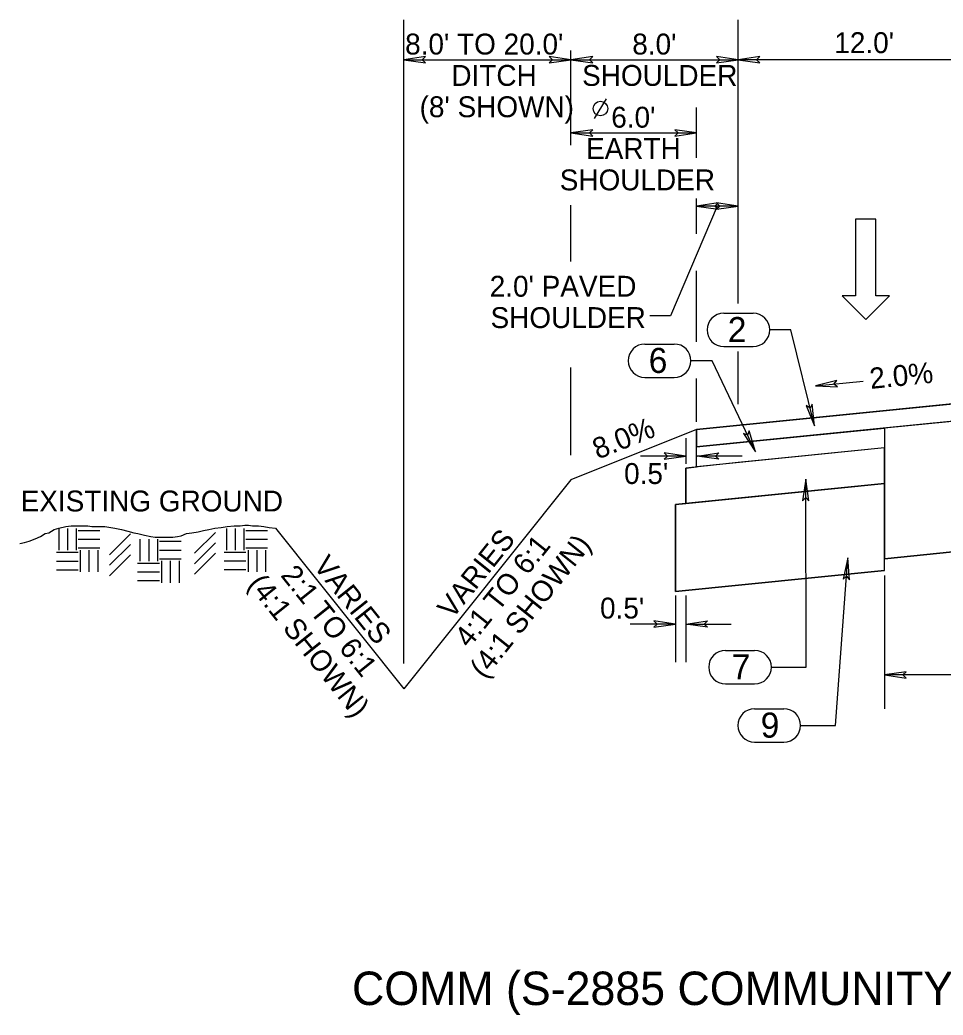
# Model space of a CAD drawing. Extents: x 2003207 to 2014043, y 843846 to 860154.
# Drawn here: x 2013826.45 to 2013870.63, y 844709.91 to 844757.53 of the extents above; entities that cross this region are included whole.
import ezdxf

# ---------------------------------------------------------------- set-up
doc = ezdxf.new("R2010")
doc.units = 0
for name, color, linetype in [('RD_EX_Road', 7, 'Continuous'), ('RD_EX_Road_txCode', 7, 'Continuous'), ('RD_QTY_Base_Course', 7, 'Continuous'), ('RD_QTY_ConcPave', 7, 'Continuous'), ('RD_QTY_Intermediate', 7, 'Continuous'), ('RD_QTY_PermVeg', 7, 'Continuous'), ('RD_QTY_Surf_Course', 7, 'Continuous'), ('RD_TX_Misc2', 7, 'Continuous'), ('RD_TX_TypSect', 7, 'Continuous'), ('RD_XS_ExGround', 7, 'Continuous')]:
    doc.layers.add(name, color=color, linetype=linetype)

msp = doc.modelspace()

# ---------------------------------------------------------------- linework, layer by layer
at = {"layer": 'RD_EX_Road'}
for p, q in [((2013881.821, 844739.393), (2013867.821, 844737.993)), ((2013867.821, 844737.993), (2013867.821, 844731.743)), ((2013881.821, 844733.143), (2013867.821, 844731.743)), ((2013867.821, 844731.743), (2013880.546, 844733.015))]:
    msp.add_line(p, q, dxfattribs=at)
at = {"layer": 'RD_QTY_Base_Course'}
for p, q in [((2013867.821, 844737.045), (2013860.821, 844736.345)), ((2013867.821, 844736.246), (2013867.821, 844737.045)), ((2013860.821, 844736.345), (2013858.321, 844736.083)), ((2013858.321, 844736.083), (2013858.321, 844734.391)), ((2013867.821, 844735.413), (2013867.821, 844736.246)), ((2013867.821, 844735.341), (2013867.821, 844735.413)), ((2013858.321, 844734.391), (2013867.821, 844735.341)), ((2013867.821, 844735.341), (2013860.821, 844734.641)), ((2013867.821, 844735.341), (2013867.821, 844735.341)), ((2013860.821, 844734.641), (2013857.821, 844734.341)), ((2013857.821, 844734.341), (2013858.321, 844734.391)), ((2013857.821, 844734.341), (2013857.821, 844730.174)), ((2013857.821, 844730.174), (2013857.821, 844734.341)), ((2013867.821, 844731.174), (2013857.821, 844730.174))]:
    msp.add_line(p, q, dxfattribs=at)
msp.add_lwpolyline([(2013857.821, 844730.174), (2013867.821, 844731.174), (2013867.821, 844735.341)], dxfattribs=at)
at = {"layer": 'RD_QTY_ConcPave'}
for p, q in [((2013858.321, 844736.083), (2013858.821, 844736.145)), ((2013858.321, 844734.391), (2013858.321, 844736.083)), ((2013867.821, 844735.341), (2013858.321, 844734.391))]:
    msp.add_line(p, q, dxfattribs=at)
at = {"layer": 'RD_QTY_Intermediate'}
for p, q in [((2013858.821, 844736.145), (2013858.821, 844737.092)), ((2013867.821, 844737.045), (2013858.821, 844736.145))]:
    msp.add_line(p, q, dxfattribs=at)
msp.add_lwpolyline([(2013858.821, 844737.092), (2013867.821, 844737.993), (2013867.821, 844737.045), (2013858.821, 844736.145)], close=True, dxfattribs=at)
at = {"layer": 'RD_QTY_PermVeg'}
for p, q in [((2013858.821, 844737.926), (2013852.821, 844735.526)), ((2013852.821, 844735.526), (2013844.821, 844725.526)), ((2013838.674, 844733.21), (2013844.821, 844725.526))]:
    msp.add_line(p, q, dxfattribs=at)
at = {"layer": 'RD_QTY_Surf_Course'}
for p, q in [((2013892.321, 844741.276), (2013858.821, 844737.926)), ((2013867.821, 844737.992), (2013858.821, 844737.092)), ((2013858.821, 844737.926), (2013858.821, 844737.092))]:
    msp.add_line(p, q, dxfattribs=at)
msp.add_lwpolyline([(2013858.821, 844737.926), (2013892.321, 844741.276), (2013925.821, 844737.926), (2013925.821, 844737.092), (2013892.321, 844740.442), (2013885.99, 844739.809), (2013885.99, 844738.976), (2013881.821, 844739.393), (2013858.821, 844737.092)], close=True, dxfattribs=at)
at = {"layer": 'RD_TX_Misc2'}
for p, q in [((2013860.134, 844743.494), (2013861.534, 844743.494)), ((2013856.361, 844742.02), (2013857.761, 844742.02)), ((2013860.134, 844741.894), (2013861.534, 844741.894)), ((2013856.361, 844740.42), (2013857.761, 844740.42)), ((2013860.21, 844727.356), (2013861.61, 844727.356)), ((2013860.21, 844725.756), (2013861.61, 844725.756)), ((2013861.609, 844724.568), (2013863.009, 844724.568)), ((2013861.609, 844722.968), (2013863.009, 844722.968))]:
    msp.add_line(p, q, dxfattribs=at)
for centre, start, end in [((2013860.134, 844742.694), 90, 270), ((2013861.534, 844742.694), 270, 90), ((2013856.361, 844741.22), 90, 270), ((2013857.761, 844741.22), 270, 90), ((2013860.21, 844726.556), 90, 270), ((2013861.61, 844726.556), 270, 90), ((2013861.609, 844723.768), 90, 270), ((2013863.009, 844723.768), 270, 90)]:
    msp.add_arc(centre, 0.8, start, end, dxfattribs=at)
at = {"layer": 'RD_TX_TypSect'}
for p, q in [((2013844.821, 844726.732), (2013844.821, 844757.53)), ((2013860.821, 844743.964), (2013860.821, 844757.53)), ((2013860.821, 844747.835), (2013860.821, 844757.53)), ((2013852.821, 844751.533), (2013852.821, 844756.062)), ((2013844.821, 844755.623), (2013852.821, 844755.623)), ((2013852.821, 844755.623), (2013860.821, 844755.623)), ((2013872.821, 844755.623), (2013860.821, 844755.623)), ((2013853.949, 844752.816), (2013854.515, 844753.759)), ((2013858.821, 844750.922), (2013858.821, 844753.33)), ((2013852.821, 844752.123), (2013858.821, 844752.123)), ((2013858.821, 844747.285), (2013858.821, 844748.978)), ((2013852.821, 844745.975), (2013852.821, 844748.661)), ((2013860.821, 844748.623), (2013858.821, 844748.623)), ((2013858.821, 844742.131), (2013858.821, 844745.518)), ((2013860.821, 844739.519), (2013860.821, 844741.656)), ((2013860.821, 844739.146), (2013860.821, 844741.562)), ((2013852.821, 844736.699), (2013852.821, 844740.897)), ((2013858.821, 844738.664), (2013858.821, 844740.367)), ((2013858.821, 844738.302), (2013858.821, 844740.229)), ((2013864.526, 844740.015), (2013866.803, 844740.243)), ((2013858.321, 844737.52), (2013858.321, 844736.291)), ((2013858.321, 844736.66), (2013856.154, 844736.66)), ((2013861.019, 844736.66), (2013858.851, 844736.66)), ((2013867.821, 844730.946), (2013867.821, 844724.555)), ((2013857.821, 844729.991), (2013857.821, 844726.789)), ((2013858.321, 844729.991), (2013858.321, 844726.789)), ((2013857.821, 844728.619), (2013855.654, 844728.619)), ((2013858.321, 844728.619), (2013860.489, 844728.619)), ((2013895.821, 844726.187), (2013867.821, 844726.187))]:
    msp.add_line(p, q, dxfattribs=at)
for points in [[(2013844.821, 844755.623), (2013845.86, 844755.473), (2013845.7, 844755.623), (2013845.86, 844755.773)], [(2013852.821, 844755.623), (2013851.783, 844755.773), (2013851.943, 844755.623), (2013851.783, 844755.473)], [(2013852.821, 844755.623), (2013853.86, 844755.473), (2013853.7, 844755.623), (2013853.86, 844755.773)], [(2013860.821, 844755.623), (2013859.783, 844755.773), (2013859.943, 844755.623), (2013859.783, 844755.473)], [(2013860.821, 844755.623), (2013861.86, 844755.473), (2013861.7, 844755.623), (2013861.86, 844755.773)], [(2013852.821, 844752.123), (2013853.86, 844751.973), (2013853.7, 844752.123), (2013853.86, 844752.273)], [(2013858.821, 844752.123), (2013857.783, 844752.273), (2013857.943, 844752.123), (2013857.783, 844751.973)], [(2013858.821, 844748.623), (2013859.86, 844748.473), (2013859.7, 844748.623), (2013859.86, 844748.773)], [(2013860.821, 844748.623), (2013859.783, 844748.773), (2013859.943, 844748.623), (2013859.783, 844748.473)], [(2013867.403, 844747.998), (2013866.443, 844747.998), (2013866.443, 844744.33), (2013865.792, 844744.33), (2013866.923, 844743.198), (2013868.055, 844744.33), (2013867.403, 844744.33)], [(2013864.526, 844740.015), (2013865.574, 844739.969), (2013865.4, 844740.102), (2013865.544, 844740.267)], [(2013864.468, 844738.101), (2013864.366, 844739.146), (2013864.259, 844738.955), (2013864.075, 844739.074)], [(2013861.654, 844736.865), (2013861.341, 844737.866), (2013861.275, 844737.657), (2013861.071, 844737.737)], [(2013858.321, 844736.66), (2013857.283, 844736.81), (2013857.443, 844736.66), (2013857.283, 844736.51)], [(2013858.851, 844736.66), (2013859.89, 844736.81), (2013859.73, 844736.66), (2013859.89, 844736.51)], [(2013864.052, 844735.553), (2013863.905, 844734.514), (2013864.054, 844734.674), (2013864.205, 844734.515)], [(2013866.069, 844731.789), (2013865.843, 844730.764), (2013866.004, 844730.912), (2013866.142, 844730.742)], [(2013857.821, 844728.619), (2013856.783, 844728.769), (2013856.943, 844728.619), (2013856.783, 844728.47)], [(2013858.321, 844728.619), (2013859.36, 844728.769), (2013859.2, 844728.619), (2013859.36, 844728.47)], [(2013867.821, 844726.187), (2013868.86, 844726.037), (2013868.7, 844726.187), (2013868.86, 844726.336)]]:
    msp.add_lwpolyline(points, close=True, dxfattribs=at)
for points in [[(2013859.821, 844748.623), (2013857.581, 844743.376), (2013856.594, 844743.376)], [(2013864.468, 844738.101), (2013863.343, 844742.694), (2013862.334, 844742.694)], [(2013861.654, 844736.865), (2013859.57, 844741.22), (2013858.561, 844741.22)], [(2013862.41, 844726.556), (2013864.075, 844726.556), (2013864.052, 844735.553)], [(2013863.809, 844723.768), (2013865.474, 844723.768), (2013866.069, 844731.789)]]:
    msp.add_lwpolyline(points, dxfattribs=at)
msp.add_circle((2013854.232, 844753.288), 0.35, dxfattribs=at)
at = {"layer": 'RD_XS_ExGround'}
for p, q in [((2013828.304, 844733.189), (2013828.304, 844732.148)), ((2013828.721, 844733.189), (2013828.721, 844732.148)), ((2013829.138, 844733.189), (2013829.138, 844732.148)), ((2013829.234, 844733.092), (2013830.276, 844733.092)), ((2013834.809, 844732.003), (2013835.809, 844733.003)), ((2013836.331, 844733.194), (2013836.331, 844732.152)), ((2013836.748, 844733.194), (2013836.748, 844732.152)), ((2013837.164, 844733.194), (2013837.164, 844732.152)), ((2013837.261, 844733.097), (2013838.303, 844733.097)), ((2013829.234, 844732.676), (2013830.276, 844732.676)), ((2013830.74, 844731.93), (2013831.74, 844732.93)), ((2013832.195, 844732.675), (2013832.195, 844731.634)), ((2013832.612, 844732.675), (2013832.612, 844731.634)), ((2013833.028, 844732.675), (2013833.028, 844731.634)), ((2013833.125, 844732.579), (2013834.166, 844732.579)), ((2013837.261, 844732.68), (2013838.303, 844732.68)), ((2013828.192, 844732.051), (2013829.234, 844732.051)), ((2013829.234, 844732.259), (2013830.276, 844732.259)), ((2013829.338, 844732.155), (2013829.338, 844731.113)), ((2013829.755, 844732.155), (2013829.755, 844731.113)), ((2013830.172, 844732.155), (2013830.172, 844731.113)), ((2013830.74, 844731.43), (2013831.74, 844732.43)), ((2013833.125, 844732.162), (2013834.166, 844732.162)), ((2013834.809, 844731.503), (2013835.809, 844732.503)), ((2013836.219, 844732.055), (2013837.261, 844732.055)), ((2013837.261, 844732.264), (2013838.303, 844732.264)), ((2013837.365, 844732.16), (2013837.365, 844731.118)), ((2013837.782, 844732.16), (2013837.782, 844731.118)), ((2013838.198, 844732.16), (2013838.198, 844731.118)), ((2013828.192, 844731.634), (2013829.234, 844731.634)), ((2013830.74, 844730.93), (2013831.74, 844731.93)), ((2013833.125, 844731.745), (2013834.166, 844731.745)), ((2013833.229, 844731.641), (2013833.229, 844730.599)), ((2013833.645, 844731.641), (2013833.645, 844730.599)), ((2013834.062, 844731.641), (2013834.062, 844730.599)), ((2013834.809, 844731.003), (2013835.809, 844732.003)), ((2013836.219, 844731.639), (2013837.261, 844731.639)), ((2013828.192, 844731.217), (2013829.234, 844731.217)), ((2013832.083, 844731.537), (2013833.125, 844731.537)), ((2013832.083, 844731.12), (2013833.125, 844731.12)), ((2013836.219, 844731.222), (2013837.261, 844731.222)), ((2013832.083, 844730.704), (2013833.125, 844730.704))]:
    msp.add_line(p, q, dxfattribs=at)
msp.add_lwpolyline([(2013826.448, 844732.477), (2013826.668, 844732.514), (2013826.888, 844732.587), (2013827.181, 844732.697), (2013827.437, 844732.807), (2013827.656, 844732.953), (2013827.839, 844732.99), (2013828.096, 844733.136), (2013828.315, 844733.21), (2013828.645, 844733.283), (2013828.901, 844733.319), (2013829.194, 844733.319), (2013829.523, 844733.319), (2013829.706, 844733.319), (2013829.889, 844733.283), (2013830.109, 844733.283), (2013830.328, 844733.283), (2013830.511, 844733.283), (2013830.804, 844733.246), (2013830.987, 844733.21), (2013831.317, 844733.136), (2013831.61, 844733.063), (2013831.902, 844732.99), (2013832.085, 844732.953), (2013832.415, 844732.88), (2013832.708, 844732.807), (2013832.927, 844732.77), (2013833.11, 844732.77), (2013833.33, 844732.77), (2013833.55, 844732.77), (2013833.769, 844732.77), (2013833.989, 844732.807), (2013834.172, 844732.843), (2013834.428, 844732.953), (2013834.684, 844732.99), (2013834.977, 844733.026), (2013835.233, 844733.1), (2013835.49, 844733.136), (2013835.782, 844733.21), (2013836.075, 844733.246), (2013836.368, 844733.283), (2013836.698, 844733.319), (2013836.99, 844733.319), (2013837.21, 844733.356), (2013837.393, 844733.356), (2013837.576, 844733.319), (2013837.869, 844733.319), (2013838.125, 844733.283), (2013838.381, 844733.246), (2013838.674, 844733.21)], dxfattribs=at)

# ---------------------------------------------------------------- texts
at = {"layer": 'RD_EX_Road_txCode'}
msp.add_text('COMM (S-2885 COMMUNITY ROAD) STA. 94+00.00 TO STA. 113+10.71', height=1.6, dxfattribs=at).set_placement((2013842.342, 844710.387))
at = {"layer": 'RD_TX_Misc2'}
for s, p in [('2', (2013860.325, 844742.109)), ('6', (2013856.54, 844740.635)), ('7', (2013860.512, 844725.971)), ('9', (2013861.899, 844723.183))]:
    msp.add_text(s, height=1.2, dxfattribs=at).set_placement(p)
at = {"layer": 'RD_TX_TypSect'}
for s, p in [("8.0' TO 20.0'", (2013844.883, 844755.873)), ("8.0'", (2013855.753, 844755.873)), ("12.0'", (2013865.423, 844755.94)), ('DITCH', (2013847.096, 844754.373)), ('SHOULDER', (2013853.353, 844754.373)), ("(8' SHOWN)", (2013845.576, 844752.873)), ("6.0'", (2013854.747, 844752.373)), ('EARTH', (2013853.542, 844750.873)), ('SHOULDER', (2013852.282, 844749.373)), ("2.0' PAVED", (2013848.932, 844744.283)), ('SHOULDER', (2013848.971, 844742.783)), ("0.5'", (2013855.362, 844735.321)), ('EXISTING GROUND', (2013826.483, 844734.006)), ("0.5'", (2013854.211, 844728.883))]:
    msp.add_text(s, height=1, dxfattribs=at).set_placement(p)
for s, rotation, p in [('2.0%', 5.7106, (2013867.159, 844739.868)), ('8.0%', 21.8014, (2013854.103, 844736.486)), ('VARIES', 51.3402, (2013847.133, 844728.816)), ('4:1 TO 6:1', 51.3402, (2013847.946, 844727.43)), ('(4:1 SHOWN)', 51.3402, (2013848.684, 844725.952)), ('VARIES', 308.6598, (2013840.45, 844731.39)), ('2:1 TO 6:1', 308.6598, (2013838.89, 844730.939)), ('(4:1 SHOWN)', 308.6598, (2013837.316, 844730.506))]:
    msp.add_text(s, height=1, rotation=rotation, dxfattribs=at).set_placement(p)

doc.saveas('drawing.dxf')
